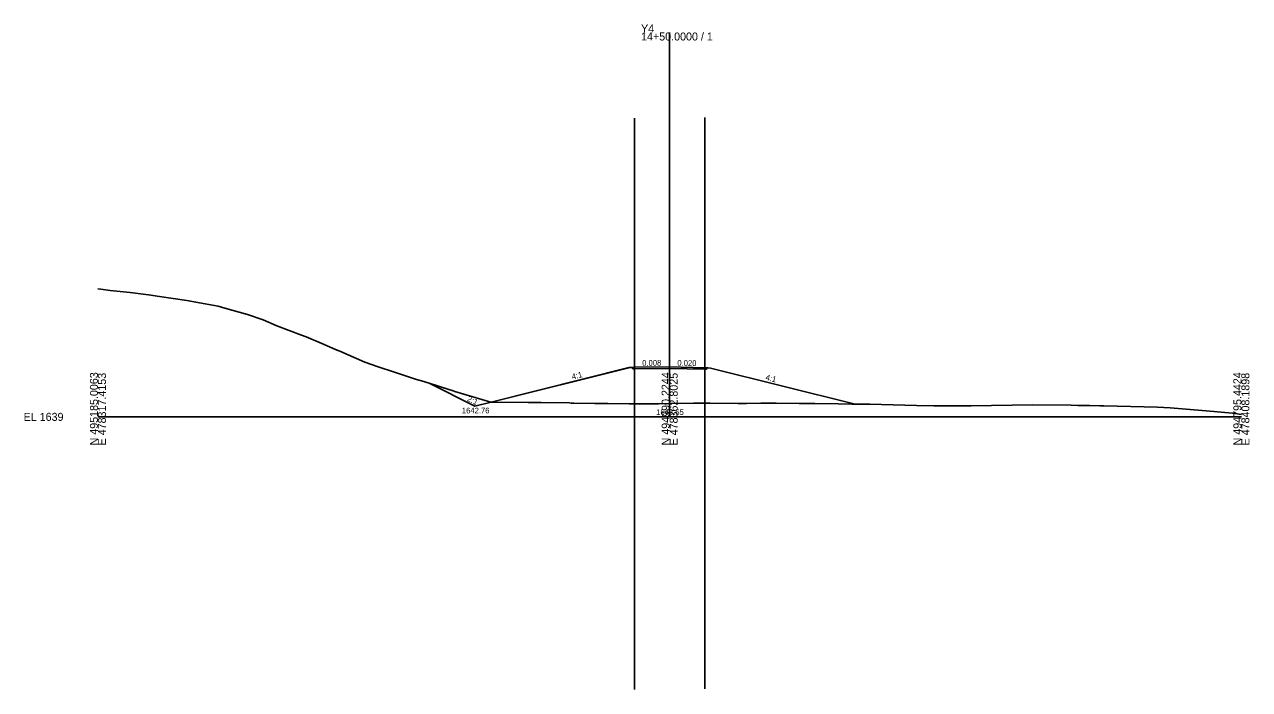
# Model space of a CAD drawing. Extents: x -26 to 403, y -10 to 5108.
# Drawn here: x -25.7 to 402.8, y 4404.6 to 4637.3 of the extents above; entities that cross this region are included whole.
import ezdxf

# ---------------------------------------------------------------- set-up
doc = ezdxf.new("R2010")
doc.units = 0
for name, color, linetype in [('Exist Cross Section Cell', 7, 'Continuous'), ('Exist XS Center Line Elevation Label', 7, 'Continuous'), ('Exist XS Ground Line', 7, 'Continuous'), ('Prop XS DDE Earthwork Shape', 7, 'Continuous'), ('Prop XS DDE Elevations', 7, 'Continuous'), ('Prop XS DDE Slope Text', 7, 'Continuous'), ('Prop XS Dump Level', 7, 'Continuous'), ('Prop XS Earthwork Shape', 7, 'Continuous'), ('Prop XS EOT Tick Mark', 7, 'Continuous'), ('Prop XS Finish Grade', 7, 'Continuous'), ('Prop XS Finish Grade Earthwork', 7, 'Continuous'), ('Prop XS Finish Grade Pavement', 7, 'Continuous'), ('Prop XS Pvmt Edge Slope', 7, 'Continuous'), ('Prop XS SE Text', 7, 'Continuous'), ('Prop XS Shoulder Borrow Shape', 7, 'Continuous'), ('Prop XS Side Slope Text', 7, 'Continuous'), ('Prop XS Subgrade Earthwork', 7, 'Continuous'), ('Scratch_Level_1', 7, 'Continuous')]:
    doc.layers.add(name, color=color, linetype=linetype)

msp = doc.modelspace()

# ---------------------------------------------------------------- linework, layer by layer
at = {"layer": 'Exist Cross Section Cell'}
for p, q in [((200, 4500), (200, 4634.52)), ((0, 4500), (200, 4500)), ((200, 4500), (400, 4500))]:
    msp.add_line(p, q, dxfattribs=at)
at = {"layer": 'Exist XS Ground Line'}
msp.add_lwpolyline([(0, 4544.84), (0.99, 4544.68), (4.26, 4544.23), (11.26, 4543.54), (17.65, 4542.7), (21.53, 4542.14), (31.04, 4540.76), (31.8, 4540.65), (34.29, 4540.15), (42.07, 4538.76), (44.43, 4538.08), (52.34, 4535.86), (57.82, 4533.95), (62.61, 4531.86), (71.21, 4528.59), (72.88, 4528.05), (78.36, 4525.63), (83.15, 4523.59), (84.6, 4522.95), (93.42, 4519.12), (97.99, 4517.5), (103.69, 4515.64), (111.38, 4513.12), (113.96, 4512.32), (122.44, 4509.71), (124.23, 4509.13), (124.82, 4508.93), (137.41, 4505.19), (150.46, 4505.05), (155.04, 4505.03), (164.94, 4504.85), (165.54, 4504.84), (166.51, 4504.82), (173.87, 4504.7), (175.58, 4504.68), (178.33, 4504.65), (185.85, 4504.57), (191.72, 4504.58), (196.12, 4504.59), (200, 4504.65), (208.35, 4504.77), (214.12, 4504.79), (223.84, 4504.72), (226.93, 4504.73), (231.89, 4504.75), (237.2, 4504.8), (245.28, 4504.71), (247.47, 4504.69), (250.78, 4504.64), (258.91, 4504.51), (263.71, 4504.39), (270, 4504.42), (286.36, 4503.95), (292.39, 4503.84), (296.07, 4503.83), (305.46, 4503.89), (326.9, 4504.19), (340.49, 4504.05), (342.78, 4504.01), (345.12, 4503.98), (346.01, 4503.97), (346.87, 4503.93), (350.45, 4503.91), (351.85, 4503.86), (370.68, 4503.41), (375.12, 4503.14), (387.67, 4502.13), (396.94, 4501.27), (400, 4500.83)], dxfattribs=at)
at = {"layer": 'Prop XS DDE Earthwork Shape'}
msp.add_lwpolyline([(137.41, 4505.19), (137.52, 4505.19), (131.79, 4503.76), (115.82, 4511.75), (122.44, 4509.71), (124.23, 4509.13), (124.82, 4508.93)], close=True, dxfattribs=at)
at = {"layer": 'Prop XS Dump Level'}
for p, q in [((187.71, 4517.36), (200, 4517.45)), ((200, 4517.45), (212.29, 4517.21))]:
    msp.add_line(p, q, dxfattribs=at)
at = {"layer": 'Prop XS Earthwork Shape'}
for p, q in [((115.82, 4511.75), (131.79, 4503.76)), ((131.79, 4503.76), (137.52, 4505.19)), ((137.52, 4505.19), (137.41, 4505.19))]:
    msp.add_line(p, q, dxfattribs=at)
msp.add_lwpolyline([(214.3, 4517.05), (264.89, 4504.4), (263.71, 4504.39), (258.91, 4504.51), (250.78, 4504.64), (247.47, 4504.69), (245.28, 4504.71), (237.2, 4504.8), (231.89, 4504.75), (226.93, 4504.73), (223.84, 4504.72), (214.12, 4504.79), (208.35, 4504.77), (200, 4504.65), (196.12, 4504.59), (191.72, 4504.58), (185.85, 4504.57), (178.33, 4504.65), (175.58, 4504.68), (173.87, 4504.7), (166.51, 4504.82), (165.54, 4504.84), (164.94, 4504.85), (155.04, 4505.03), (150.46, 4505.05), (137.52, 4505.19), (185.7, 4517.22), (186.69, 4517.29), (187.16, 4516.81), (187.71, 4516.81), (200, 4516.91), (212.29, 4516.66), (212.84, 4516.65), (213.32, 4517.12)], close=True, dxfattribs=at)
msp.add_lwpolyline([(137.41, 4505.19), (124.82, 4508.93), (124.23, 4509.13), (122.44, 4509.71), (115.82, 4511.75)], dxfattribs=at)
at = {"layer": 'Prop XS EOT Tick Mark'}
for p, q in [((187.71, 4517.36), (187.71, 4518.36)), ((212.29, 4517.21), (212.29, 4518.21))]:
    msp.add_line(p, q, dxfattribs=at)
at = {"layer": 'Prop XS Finish Grade'}
for p, q in [((187.71, 4517.36), (186.69, 4517.29)), ((212.29, 4517.21), (213.32, 4517.12))]:
    msp.add_line(p, q, dxfattribs=at)
at = {"layer": 'Prop XS Finish Grade Earthwork'}
for p, q in [((185.7, 4517.21), (137.52, 4505.19)), ((186.69, 4517.29), (185.7, 4517.22)), ((213.32, 4517.12), (214.3, 4517.05)), ((214.3, 4517.05), (264.89, 4504.4)), ((131.79, 4503.76), (115.82, 4511.75)), ((131.79, 4503.76), (137.52, 4505.19))]:
    msp.add_line(p, q, dxfattribs=at)
at = {"layer": 'Prop XS Finish Grade Pavement'}
for p, q in [((187.71, 4517.36), (200, 4517.45)), ((200, 4517.45), (212.29, 4517.21))]:
    msp.add_line(p, q, dxfattribs=at)
at = {"layer": 'Prop XS Pvmt Edge Slope'}
for p, q in [((187.71, 4517.36), (187.16, 4516.81)), ((212.29, 4517.21), (212.84, 4516.65))]:
    msp.add_line(p, q, dxfattribs=at)
at = {"layer": 'Prop XS Shoulder Borrow Shape'}
for points in [[(187.71, 4517.36), (186.69, 4517.29), (187.16, 4516.81)], [(212.29, 4517.21), (213.32, 4517.12), (212.84, 4516.65)]]:
    msp.add_lwpolyline(points, close=True, dxfattribs=at)
at = {"layer": 'Prop XS Subgrade Earthwork'}
for p, q in [((187.16, 4516.81), (186.69, 4517.29)), ((187.71, 4516.81), (187.16, 4516.81)), ((200, 4516.91), (187.71, 4516.81)), ((212.29, 4516.66), (200, 4516.91)), ((212.84, 4516.65), (213.32, 4517.12)), ((212.29, 4516.66), (212.84, 4516.65))]:
    msp.add_line(p, q, dxfattribs=at)
at = {"layer": 'Scratch_Level_1'}
for p, q in [((187.71, 4604.57), (187.71, 4404.57)), ((212.29, 4604.79), (212.29, 4404.79))]:
    msp.add_line(p, q, dxfattribs=at)

# ---------------------------------------------------------------- texts
at = {"layer": 'Exist Cross Section Cell'}
for s, p in [('Y4', (190, 4634.52)), ('14+50.0000 / 1', (190, 4631.72)), ('EL 1639', (-26, 4498.6))]:
    msp.add_text(s, height=2.8, dxfattribs=at).set_placement(p)
for s, p in [('N 495185.0063', (0, 4490)), ('E 478317.4153', (2.8, 4490)), ('N 494990.2244', (200, 4490)), ('E 478362.8025', (202.8, 4490)), ('N 494795.4424', (400, 4490)), ('E 478408.1898', (402.8, 4490))]:
    msp.add_text(s, height=2.8, rotation=90, dxfattribs=at).set_placement(p)
at = {"layer": 'Exist XS Center Line Elevation Label'}
msp.add_text('1643.65', height=2, dxfattribs=at).set_placement((195.28, 4500.65))
at = {"layer": 'Prop XS DDE Elevations'}
msp.add_text('1642.76', height=2, dxfattribs=at).set_placement((127.3, 4501.21))
at = {"layer": 'Prop XS DDE Slope Text'}
msp.add_text('2:1', height=2, rotation=333.4355, dxfattribs=at).set_placement((128.99, 4505.67))
at = {"layer": 'Prop XS Dump Level'}
for p in [(185.7, 4517.18), (214.3, 4517.01)]:
    msp.add_text('Case1', height=0.04, dxfattribs=at).set_placement(p)
at = {"layer": 'Prop XS SE Text'}
for s, rotation, p in [('0.008', 0.4488, (190.39, 4517.88)), ('0.020', 358.8542, (202.66, 4517.9))]:
    msp.add_text(s, height=2, rotation=rotation, dxfattribs=at).set_placement(p)
at = {"layer": 'Prop XS Side Slope Text'}
for rotation, p in [(14.0094, (166, 4513.04)), (345.9638, (233.41, 4512.94))]:
    msp.add_text('4:1', height=2, rotation=rotation, dxfattribs=at).set_placement(p)

doc.saveas('drawing.dxf')
